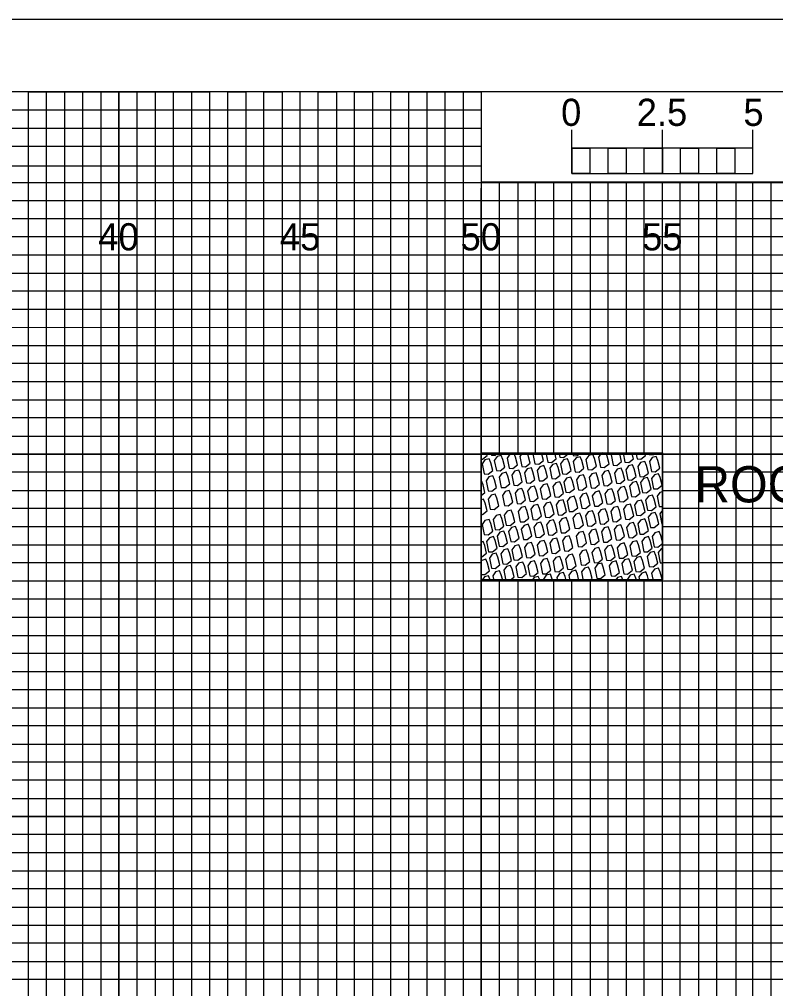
# Model space of a CAD drawing. Extents: x -7 to 193, y -2 to 107.
# Drawn here: x 117.25 to 138.13, y 80.25 to 107 of the extents above; entities that cross this region are included whole.
import ezdxf

# ---------------------------------------------------------------- set-up
doc = ezdxf.new("R2010")
doc.units = 0
for name, color, linetype in [('Exist XS Center Line Elevation Label', 7, 'Continuous'), ('Old_Level_1', 7, 'Continuous'), ('Prop Vertical Profile Curve Label', 7, 'Continuous'), ('Prop XS Bar Scale Labels', 7, 'Continuous'), ('Prop XS Offset Labels', 7, 'Continuous'), ('Sheet Cross Section CELL', 7, 'Continuous'), ('Sheet Cross Section Grid Major CELL', 7, 'Continuous'), ('Sheet Cross Section Grid Middle CELL', 7, 'Continuous'), ('Sheet Cross Section Grid Minor 1 CELL', 7, 'Continuous'), ('Sheet Cross Section Grid Minor 2 CELL', 7, 'Continuous'), ('Sheet Cross Section Scale CELL', 7, 'Continuous'), ('Sheet Cutting Line CELL', 7, 'Continuous'), ('Sheet DOT Grid CELL', 7, 'Continuous'), ('Sheet Plot Border Inside CELL', 7, 'Continuous'), ('Sheet Plot Border Outside CELL', 7, 'Continuous')]:
    doc.layers.add(name, color=color, linetype=linetype)

msp = doc.modelspace()

# ---------------------------------------------------------------- linework, layer by layer
at = {"layer": 'Old_Level_1'}
for points in [[(130, 94.864), (130.035, 94.862), (130.164, 94.965), (130.146, 95.034)], [(130.268, 95.034), (130.28, 94.976), (130.385, 94.968), (130.467, 95.034)], [(130.643, 95.034), (130.645, 95.022), (130.751, 95.014), (130.775, 95.034)], [(131.133, 95.034), (131.062, 94.936), (131.118, 94.656), (131.223, 94.648), (131.353, 94.752), (131.298, 94.962), (131.269, 95.034)], [(131.443, 95.034), (131.428, 95.012), (131.483, 94.732), (131.589, 94.725), (131.718, 94.828), (131.665, 95.034)], [(131.783, 95.034), (131.834, 94.778), (131.939, 94.77), (132.069, 94.874), (132.027, 95.034)], [(132.145, 95.034), (132.169, 94.915), (132.274, 94.907), (132.404, 95.011), (132.398, 95.034)], [(132.52, 95.034), (132.535, 94.961), (132.64, 94.953), (132.741, 95.034)], [(133.348, 95.034), (133.314, 95.025), (133.237, 94.919), (133.293, 94.639), (133.398, 94.631), (133.528, 94.734), (133.473, 94.945), (133.437, 95.034)], [(133.625, 95.034), (133.586, 94.98), (133.641, 94.7), (133.747, 94.692), (133.876, 94.796), (133.822, 95.006), (133.811, 95.034)], [(133.916, 95.034), (133.967, 94.778), (134.072, 94.77), (134.202, 94.874), (134.16, 95.034)], [(134.269, 95.034), (134.302, 94.869), (134.407, 94.862), (134.537, 94.965), (134.519, 95.034)], [(134.629, 95.034), (134.637, 94.991), (134.742, 94.984), (134.805, 95.034)], [(130, 93.861), (130.103, 93.944), (130.049, 94.154), (130.004, 94.264), (130, 94.263)], [(132.336, 93.95), (132.441, 93.942), (132.571, 94.046), (132.516, 94.256), (132.471, 94.366), (132.357, 94.336), (132.28, 94.23), (132.336, 93.95)], [(132.685, 94.012), (132.79, 94.004), (132.919, 94.107), (132.865, 94.318), (132.82, 94.427), (132.706, 94.398), (132.629, 94.292), (132.685, 94.012)], [(130.64, 93.58), (130.745, 93.572), (130.874, 93.675), (130.82, 93.886), (130.775, 93.996), (130.661, 93.966), (130.584, 93.86), (130.64, 93.58)], [(130.988, 93.641), (131.094, 93.634), (131.223, 93.737), (131.169, 93.947), (131.123, 94.057), (131.01, 94.028), (130.933, 93.921), (130.988, 93.641)], [(133.122, 93.569), (133.227, 93.561), (133.357, 93.664), (133.302, 93.875), (133.257, 93.985), (133.144, 93.955), (133.066, 93.849), (133.122, 93.569)], [(133.471, 93.63), (133.576, 93.623), (133.705, 93.726), (133.651, 93.937), (133.606, 94.046), (133.492, 94.017), (133.415, 93.91), (133.471, 93.63)], [(133.819, 93.692), (133.925, 93.684), (134.054, 93.787), (134, 93.998), (133.954, 94.108), (133.841, 94.078), (133.764, 93.972), (133.819, 93.692)], [(135, 93.962), (134.933, 93.945), (134.856, 93.839), (134.911, 93.559), (135, 93.552)], [(130, 93.34), (130.035, 93.338), (130.164, 93.441), (130.11, 93.651), (130.065, 93.761), (130, 93.744)], [(131.774, 93.26), (131.88, 93.252), (132.009, 93.356), (131.955, 93.566), (131.91, 93.676), (131.796, 93.647), (131.719, 93.54), (131.774, 93.26)], [(132.123, 93.322), (132.228, 93.314), (132.358, 93.417), (132.303, 93.628), (132.258, 93.737), (132.144, 93.708), (132.067, 93.602), (132.123, 93.322)], [(131.426, 93.199), (131.531, 93.191), (131.661, 93.294), (131.606, 93.505), (131.561, 93.614), (131.447, 93.585), (131.37, 93.479), (131.426, 93.199)], [(135.005, 93.451), (134.932, 93.351), (134.988, 93.071), (135.005, 93.07)], [(132.675, 92.454), (132.781, 92.446), (132.91, 92.549), (132.856, 92.76), (132.81, 92.869), (132.697, 92.84), (132.62, 92.733), (132.675, 92.454)], [(133.024, 92.515), (133.129, 92.507), (133.259, 92.611), (133.204, 92.821), (133.159, 92.931), (133.045, 92.901), (132.968, 92.795), (133.024, 92.515)], [(130, 92.165), (130.019, 92.164), (130.149, 92.267), (130.095, 92.478), (130.049, 92.587), (130, 92.575)], [(131.25, 92.145), (131.356, 92.137), (131.485, 92.24), (131.431, 92.451), (131.386, 92.561), (131.272, 92.531), (131.195, 92.425), (131.25, 92.145)], [(134.159, 92.195), (134.264, 92.188), (134.393, 92.291), (134.339, 92.501), (134.294, 92.611), (134.18, 92.582), (134.103, 92.475), (134.159, 92.195)], [(130.902, 92.083), (131.007, 92.076), (131.137, 92.179), (131.082, 92.389), (131.037, 92.499), (130.923, 92.47), (130.846, 92.363), (130.902, 92.083)], [(133.461, 92.072), (133.567, 92.065), (133.696, 92.168), (133.642, 92.379), (133.597, 92.488), (133.483, 92.459), (133.406, 92.352), (133.461, 92.072)], [(133.81, 92.134), (133.915, 92.126), (134.045, 92.229), (133.99, 92.44), (133.945, 92.55), (133.831, 92.52), (133.754, 92.414), (133.81, 92.134)], [(135, 92.4), (134.963, 92.39), (134.886, 92.284), (134.942, 92.004), (135, 92)], [(130, 91.683), (130.096, 91.676), (130.225, 91.779), (130.171, 91.99), (130.126, 92.1), (130.012, 92.07), (130, 92.054)], [(131.688, 91.702), (131.793, 91.694), (131.923, 91.798), (131.868, 92.008), (131.823, 92.118), (131.709, 92.089), (131.632, 91.982), (131.688, 91.702)], [(132.036, 91.764), (132.142, 91.756), (132.271, 91.859), (132.217, 92.07), (132.172, 92.179), (132.058, 92.15), (131.981, 92.044), (132.036, 91.764)], [(132.385, 91.825), (132.49, 91.817), (132.62, 91.921), (132.565, 92.131), (132.52, 92.241), (132.407, 92.211), (132.329, 92.105), (132.385, 91.825)], [(130.583, 91.549), (130.552, 91.67), (130.506, 91.779), (130.393, 91.75), (130.316, 91.644), (130.334, 91.549)], [(130.832, 91.549), (130.911, 91.612), (130.856, 91.822), (130.811, 91.932), (130.697, 91.903), (130.62, 91.796), (130.669, 91.549)], [(132.689, 91.549), (132.654, 91.685), (132.609, 91.795), (132.495, 91.765), (132.418, 91.659), (132.44, 91.549)], [(133.037, 91.549), (133.059, 91.566), (133.004, 91.776), (132.959, 91.886), (132.846, 91.857), (132.768, 91.75), (132.809, 91.549)], [(134.99, 91.549), (134.939, 91.746), (134.894, 91.856), (134.78, 91.826), (134.703, 91.72), (134.737, 91.549)], [(130.24, 91.549), (130.202, 91.642), (130.088, 91.613), (130.041, 91.549)], [(131.605, 91.549), (131.573, 91.627), (131.459, 91.598), (131.424, 91.549)], [(131.961, 91.549), (131.953, 91.578), (131.908, 91.688), (131.794, 91.659), (131.717, 91.552), (131.718, 91.549)], [(132.338, 91.549), (132.319, 91.624), (132.274, 91.734), (132.16, 91.704), (132.083, 91.598), (132.093, 91.549)], [(133.912, 91.534), (133.873, 91.627), (133.76, 91.598), (133.713, 91.534)], [(134.277, 91.549), (134.269, 91.578), (134.224, 91.688), (134.11, 91.659), (134.033, 91.552), (134.034, 91.549)], [(134.616, 91.534), (134.589, 91.639), (134.544, 91.749), (134.43, 91.72), (134.353, 91.613), (134.369, 91.534)]]:
    msp.add_lwpolyline(points, dxfattribs=at)
for points in [[(130.417, 94.549), (130.522, 94.542), (130.652, 94.645), (130.597, 94.855), (130.552, 94.965), (130.438, 94.936), (130.361, 94.829)], [(130.417, 94.549), (130.522, 94.542), (130.652, 94.645), (130.597, 94.855), (130.552, 94.965), (130.438, 94.936), (130.361, 94.829)], [(130.767, 94.61), (130.873, 94.603), (131.002, 94.706), (130.948, 94.916), (130.903, 95.026), (130.789, 94.997), (130.712, 94.89)], [(130.767, 94.61), (130.873, 94.603), (131.002, 94.706), (130.948, 94.916), (130.903, 95.026), (130.789, 94.997), (130.712, 94.89)], [(132.944, 94.577), (133.05, 94.569), (133.179, 94.673), (133.125, 94.883), (133.079, 94.993), (132.966, 94.963), (132.889, 94.857)], [(130.082, 94.458), (130.187, 94.45), (130.317, 94.553), (130.262, 94.764), (130.217, 94.874), (130.103, 94.844), (130.026, 94.738)], [(130.082, 94.458), (130.187, 94.45), (130.317, 94.553), (130.262, 94.764), (130.217, 94.874), (130.103, 94.844), (130.026, 94.738)], [(131.945, 94.33), (132.05, 94.322), (132.18, 94.425), (132.126, 94.636), (132.08, 94.746), (131.967, 94.716), (131.89, 94.61)], [(132.247, 94.454), (132.352, 94.446), (132.482, 94.55), (132.427, 94.76), (132.382, 94.87), (132.269, 94.841), (132.191, 94.734)], [(132.596, 94.516), (132.701, 94.508), (132.83, 94.611), (132.776, 94.822), (132.731, 94.931), (132.617, 94.902), (132.54, 94.796)], [(134.043, 94.29), (134.148, 94.283), (134.278, 94.386), (134.223, 94.596), (134.178, 94.706), (134.064, 94.677), (133.987, 94.57)], [(134.378, 94.382), (134.483, 94.374), (134.613, 94.477), (134.558, 94.688), (134.513, 94.797), (134.4, 94.768), (134.322, 94.662)], [(134.698, 94.519), (134.803, 94.511), (134.933, 94.614), (134.878, 94.825), (134.833, 94.935), (134.719, 94.905), (134.642, 94.799)], [(130.551, 94.084), (130.656, 94.076), (130.786, 94.179), (130.731, 94.39), (130.686, 94.5), (130.572, 94.47), (130.495, 94.364)], [(130.899, 94.145), (131.005, 94.138), (131.134, 94.241), (131.08, 94.451), (131.035, 94.561), (130.921, 94.532), (130.844, 94.425)], [(131.248, 94.207), (131.353, 94.199), (131.483, 94.302), (131.428, 94.513), (131.383, 94.623), (131.269, 94.593), (131.192, 94.487)], [(131.597, 94.268), (131.702, 94.261), (131.831, 94.364), (131.777, 94.574), (131.732, 94.684), (131.618, 94.655), (131.541, 94.548)], [(133.033, 94.073), (133.138, 94.065), (133.268, 94.169), (133.214, 94.379), (133.168, 94.489), (133.055, 94.459), (132.978, 94.353)], [(133.382, 94.134), (133.487, 94.127), (133.617, 94.23), (133.562, 94.441), (133.517, 94.55), (133.403, 94.521), (133.326, 94.414)], [(133.73, 94.196), (133.836, 94.188), (133.965, 94.291), (133.911, 94.502), (133.866, 94.612), (133.752, 94.582), (133.675, 94.476)], [(134.759, 94.046), (134.864, 94.039), (134.994, 94.142), (134.939, 94.352), (134.894, 94.462), (134.78, 94.433), (134.703, 94.326)], [(130.188, 93.985), (130.294, 93.978), (130.423, 94.081), (130.369, 94.291), (130.324, 94.401), (130.21, 94.372), (130.133, 94.265)], [(131.685, 93.764), (131.791, 93.757), (131.92, 93.86), (131.866, 94.07), (131.821, 94.18), (131.707, 94.151), (131.63, 94.044)], [(132.034, 93.826), (132.139, 93.818), (132.269, 93.921), (132.214, 94.132), (132.169, 94.241), (132.055, 94.212), (131.978, 94.106)], [(134.15, 93.833), (134.255, 93.825), (134.384, 93.928), (134.33, 94.139), (134.285, 94.249), (134.171, 94.219), (134.094, 94.113)], [(134.454, 93.94), (134.56, 93.932), (134.689, 94.035), (134.635, 94.246), (134.589, 94.355), (134.476, 94.326), (134.399, 94.22)], [(130.249, 93.482), (130.355, 93.475), (130.484, 93.578), (130.43, 93.788), (130.385, 93.898), (130.271, 93.869), (130.194, 93.762)], [(131.337, 93.703), (131.442, 93.695), (131.572, 93.798), (131.517, 94.009), (131.472, 94.119), (131.358, 94.089), (131.281, 93.983)], [(132.773, 93.507), (132.879, 93.5), (133.008, 93.603), (132.954, 93.814), (132.909, 93.923), (132.795, 93.894), (132.718, 93.787)], [(132.428, 93.421), (132.533, 93.414), (132.663, 93.517), (132.608, 93.728), (132.563, 93.837), (132.449, 93.808), (132.372, 93.701)], [(134.287, 93.315), (134.392, 93.307), (134.521, 93.41), (134.467, 93.621), (134.422, 93.731), (134.308, 93.701), (134.231, 93.595)], [(134.591, 93.452), (134.697, 93.444), (134.826, 93.547), (134.772, 93.758), (134.727, 93.868), (134.613, 93.838), (134.536, 93.732)], [(130.691, 93.04), (130.796, 93.033), (130.926, 93.136), (130.872, 93.346), (130.826, 93.456), (130.713, 93.427), (130.636, 93.32)], [(131.077, 93.137), (131.182, 93.13), (131.312, 93.233), (131.257, 93.443), (131.212, 93.553), (131.099, 93.524), (131.022, 93.417)], [(132.586, 92.958), (132.692, 92.95), (132.821, 93.053), (132.767, 93.264), (132.722, 93.373), (132.608, 93.344), (132.531, 93.238)], [(132.935, 93.019), (133.04, 93.011), (133.17, 93.115), (133.115, 93.325), (133.07, 93.435), (132.956, 93.405), (132.879, 93.299)], [(133.284, 93.081), (133.389, 93.073), (133.518, 93.176), (133.464, 93.387), (133.419, 93.496), (133.305, 93.467), (133.228, 93.361)], [(133.632, 93.142), (133.737, 93.134), (133.867, 93.238), (133.813, 93.448), (133.767, 93.558), (133.654, 93.528), (133.577, 93.422)], [(133.981, 93.203), (134.086, 93.196), (134.216, 93.299), (134.161, 93.51), (134.116, 93.619), (134.002, 93.59), (133.925, 93.483)], [(134.668, 92.979), (134.773, 92.972), (134.902, 93.075), (134.848, 93.285), (134.803, 93.395), (134.689, 93.366), (134.612, 93.259)], [(130.082, 92.781), (130.187, 92.774), (130.317, 92.877), (130.262, 93.087), (130.217, 93.197), (130.103, 93.168), (130.026, 93.061)], [(130.386, 92.918), (130.492, 92.911), (130.621, 93.014), (130.567, 93.225), (130.522, 93.334), (130.408, 93.305), (130.331, 93.198)], [(131.51, 92.71), (131.615, 92.703), (131.745, 92.806), (131.69, 93.016), (131.645, 93.126), (131.532, 93.097), (131.455, 92.99)], [(131.859, 92.772), (131.964, 92.764), (132.094, 92.867), (132.039, 93.078), (131.994, 93.188), (131.88, 93.158), (131.803, 93.052)], [(132.207, 92.833), (132.313, 92.826), (132.442, 92.929), (132.388, 93.139), (132.343, 93.249), (132.229, 93.22), (132.152, 93.113)], [(134.07, 92.699), (134.175, 92.692), (134.304, 92.795), (134.25, 93.006), (134.205, 93.115), (134.091, 93.086), (134.014, 92.979)], [(134.378, 92.796), (134.483, 92.789), (134.613, 92.892), (134.558, 93.103), (134.513, 93.212), (134.4, 93.183), (134.322, 93.076)], [(130.493, 92.461), (130.598, 92.453), (130.728, 92.557), (130.673, 92.767), (130.628, 92.877), (130.515, 92.848), (130.437, 92.741)], [(130.813, 92.587), (130.918, 92.58), (131.048, 92.683), (130.993, 92.893), (130.948, 93.003), (130.834, 92.974), (130.757, 92.867)], [(131.162, 92.649), (131.267, 92.641), (131.396, 92.744), (131.342, 92.955), (131.297, 93.065), (131.183, 93.035), (131.106, 92.929)], [(133.372, 92.576), (133.478, 92.569), (133.607, 92.672), (133.553, 92.883), (133.508, 92.992), (133.394, 92.963), (133.317, 92.856)], [(133.721, 92.638), (133.826, 92.63), (133.956, 92.733), (133.901, 92.944), (133.856, 93.054), (133.742, 93.024), (133.665, 92.918)], [(134.774, 92.446), (134.879, 92.438), (135.009, 92.541), (134.955, 92.752), (134.909, 92.862), (134.796, 92.832), (134.719, 92.726)], [(130.204, 92.309), (130.309, 92.301), (130.438, 92.404), (130.384, 92.615), (130.339, 92.725), (130.225, 92.695), (130.148, 92.589)], [(131.599, 92.206), (131.704, 92.199), (131.834, 92.302), (131.779, 92.512), (131.734, 92.622), (131.62, 92.593), (131.543, 92.486)], [(131.948, 92.268), (132.053, 92.26), (132.182, 92.363), (132.128, 92.574), (132.083, 92.683), (131.969, 92.654), (131.892, 92.548)], [(132.296, 92.329), (132.401, 92.321), (132.531, 92.425), (132.477, 92.635), (132.431, 92.745), (132.318, 92.716), (132.241, 92.609)], [(134.485, 92.309), (134.59, 92.301), (134.72, 92.404), (134.665, 92.615), (134.62, 92.725), (134.506, 92.695), (134.429, 92.589)], [(130.6, 91.973), (130.705, 91.966), (130.835, 92.069), (130.78, 92.279), (130.735, 92.389), (130.621, 92.36), (130.544, 92.253)], [(132.763, 91.943), (132.868, 91.935), (132.998, 92.038), (132.944, 92.249), (132.898, 92.359), (132.785, 92.329), (132.708, 92.223)], [(133.113, 92.011), (133.218, 92.003), (133.348, 92.106), (133.293, 92.317), (133.248, 92.427), (133.134, 92.397), (133.057, 92.291)], [(134.637, 91.897), (134.742, 91.889), (134.872, 91.993), (134.817, 92.203), (134.772, 92.313), (134.659, 92.284), (134.581, 92.177)], [(130.28, 91.851), (130.385, 91.844), (130.515, 91.947), (130.46, 92.158), (130.415, 92.267), (130.301, 92.238), (130.224, 92.131)], [(131.011, 91.608), (131.116, 91.6), (131.246, 91.703), (131.191, 91.914), (131.146, 92.023), (131.033, 91.994), (130.955, 91.888)], [(131.339, 91.641), (131.445, 91.633), (131.574, 91.736), (131.52, 91.947), (131.474, 92.056), (131.361, 92.027), (131.284, 91.921)], [(133.586, 91.638), (133.691, 91.63), (133.821, 91.734), (133.766, 91.944), (133.721, 92.054), (133.607, 92.024), (133.53, 91.918)], [(133.936, 91.699), (134.042, 91.691), (134.171, 91.795), (134.117, 92.005), (134.071, 92.115), (133.958, 92.085), (133.881, 91.979)], [(134.271, 91.76), (134.377, 91.752), (134.506, 91.856), (134.452, 92.066), (134.407, 92.176), (134.293, 92.146), (134.216, 92.04)], [(133.19, 91.577), (133.295, 91.569), (133.425, 91.673), (133.37, 91.883), (133.325, 91.993), (133.211, 91.963), (133.134, 91.857)]]:
    msp.add_lwpolyline(points, close=True, dxfattribs=at)
at = {"layer": 'Prop Vertical Profile Curve Label'}
for p, q in [((130, 95.034), (135, 95.034)), ((130, 91.534), (130, 95.034)), ((135, 95.034), (135, 91.534)), ((135, 91.534), (130, 91.534))]:
    msp.add_line(p, q, dxfattribs=at)
at = {"layer": 'Sheet Cross Section CELL'}
for points in [[(160, 105), (0, 105), (0, 0), (160, 0)], [(140, 105), (130, 105), (130, 102.515), (140, 102.515)]]:
    msp.add_lwpolyline(points, close=True, dxfattribs=at)
at = {"layer": 'Sheet Cross Section Grid Major CELL'}
for p, q in [((125, 105), (120, 105)), ((120, 105), (120, 0)), ((125, 0), (125, 105)), ((130, 105), (130, 0)), ((135, 0), (135, 102.5))]:
    msp.add_line(p, q, dxfattribs=at)
for points in [[(0, 100), (160, 100), (160, 95), (0, 95)], [(0, 90), (160, 90), (160, 85), (0, 85)]]:
    msp.add_lwpolyline(points, dxfattribs=at)
at = {"layer": 'Sheet Cross Section Grid Middle CELL'}
for points in [[(92.5, 0), (97.5, 0), (97.5, 105), (102.5, 105), (102.5, 0), (107.5, 0), (107.5, 105), (112.5, 105), (112.5, 0), (117.5, 0), (117.5, 105), (122.5, 105), (122.5, 0), (127.5, 0), (127.5, 105), (129.965, 105), (130, 105), (130, 102.5), (132.495, 102.5), (132.495, 95.034)], [(0, 102.5), (137.5, 102.5)], [(132.495, 91.5), (132.495, 0), (137.5, 0), (137.5, 102.5), (142.5, 102.5), (142.5, 0), (147.5, 0), (147.5, 102.5), (152.5, 102.5), (152.5, 0), (157.5, 0), (157.5, 102.5)], [(135, 92.5), (160, 92.5), (160, 97.5), (0, 97.5)], [(0, 92.5), (130, 92.5)], [(0, 82.5), (160, 82.5), (160, 87.5), (0, 87.5)]]:
    msp.add_lwpolyline(points, dxfattribs=at)
at = {"layer": 'Sheet Cross Section Grid Minor 1 CELL'}
for p, q in [((0, 104.5), (130, 104.5)), ((130, 104.5), (130, 103.99)), ((130, 103.99), (0, 103.99)), ((0, 103.5), (130, 103.5)), ((130, 103.5), (130, 102.945)), ((130, 102.945), (0, 102.945)), ((0, 102), (160, 102))]:
    msp.add_line(p, q, dxfattribs=at)
for points in [[(0, 101.5), (135, 101.5), (160, 101.5), (160, 101), (0, 101)], [(0, 100.5), (160, 100.5), (160, 99.5), (0, 99.5)], [(0, 99), (160, 99), (160, 98.5), (0, 98.49)], [(0, 98), (160, 98), (160, 97), (0, 97)], [(0, 96.5), (160, 96.5), (160, 96), (0, 96)], [(0, 95.5), (160, 95.5), (160, 94.5), (135, 94.5)], [(130, 94.5), (0, 94.5)], [(0, 94), (130, 94)], [(135, 94), (160, 94), (160, 93.5), (135, 93.5)], [(130, 93.5), (0, 93.5)], [(0, 93), (130, 93)], [(135, 93), (160, 93), (160, 92), (135, 92)], [(130, 92), (0, 92)], [(0, 91.5), (160, 91.5), (160, 91), (0, 91)], [(0, 90.5), (160, 90.5), (160, 89.5), (0, 89.5)], [(0, 89), (160, 89), (160, 88.5), (0, 88.5)], [(0, 88), (160, 88), (160, 86.975), (160, 86.5), (160, 86), (0, 86)], [(0, 87), (160, 87), (160, 86.5), (0, 86.5)], [(0, 85.5), (160, 85.5), (160, 84.5), (0, 84.515)], [(0, 84.515), (160, 84.5), (160, 84), (0, 84)], [(0, 83.5), (160, 83.5), (160, 83), (0, 83)], [(0, 82), (160, 82), (160, 81.5), (0, 81.5)], [(0, 81), (160, 81), (160, 80.5), (0, 80.5)]]:
    msp.add_lwpolyline(points, dxfattribs=at)
at = {"layer": 'Sheet Cross Section Grid Minor 2 CELL'}
for p, q in [((133.5, 102.5), (133.005, 102.5)), ((133.005, 102.5), (133.005, 95.034)), ((133.5, 95.034), (133.5, 102.5)), ((134.5, 102.5), (134, 102.5)), ((134, 102.5), (134, 95.034)), ((134.5, 95.034), (134.5, 102.5)), ((133.005, 91.5), (133.005, 0)), ((133.5, 0), (133.5, 91.5)), ((134, 91.5), (134, 0)), ((134.5, 0), (134.5, 91.5))]:
    msp.add_line(p, q, dxfattribs=at)
for points in [[(117.5, 0), (118, 0), (118, 105), (118.5, 105), (118.5, 0)], [(118.5, 0), (119, 0), (119, 105), (119.5, 105), (119.5, 0)], [(120, 0), (120.5, 0), (120.5, 105), (121, 105), (121, 0)], [(121, 0), (121.5, 0), (121.5, 105), (122, 105), (122, 0)], [(122.5, 0), (123, 0), (123, 105), (123.5, 105), (123.5, 0)], [(123.5, 0), (124, 0), (124, 105), (124.5, 105), (124.5, 0)], [(125, 0), (125.5, 0), (125.5, 105), (126, 105), (126, 0)], [(126, 0), (126.5, 0), (126.5, 105), (127, 105), (127, 0)], [(127.5, 0), (128, 0), (128, 105), (128.5, 105), (128.5, 0)], [(128.5, 0), (129, 0), (129, 105), (129.5, 105), (129.5, 0)], [(130.5, 95.034), (130.5, 102.5), (131.01, 102.5), (131.01, 95.034)], [(131.5, 95.034), (131.5, 102.5), (131.995, 102.5), (131.995, 95.034)], [(135, 0), (135.49, 0), (135.49, 102.5), (136, 102.5), (136, 0)], [(136, 0), (136.5, 0), (136.5, 102.5), (137.025, 102.5), (137.025, 0)], [(137.5, 0), (138, 0), (138, 102.5), (138.5, 102.5), (138.5, 0)], [(130, 0), (130.5, 0), (130.5, 91.5)], [(131, 0), (131.5, 0), (131.5, 91.5)], [(131.01, 91.5), (131.01, 0)], [(131.995, 91.5), (131.995, 0)]]:
    msp.add_lwpolyline(points, dxfattribs=at)
at = {"layer": 'Sheet Cross Section Scale CELL'}
for p, q in [((132.5, 102.745), (132.5, 103.95)), ((132.5, 103.45), (132.5, 103.95)), ((135, 102.745), (135, 103.95)), ((137.5, 102.745), (137.5, 103.95)), ((137.5, 103.45), (137.5, 103.95))]:
    msp.add_line(p, q, dxfattribs=at)
for points in [[(137.5, 103.45), (132.5, 103.45), (132.5, 102.745), (137.5, 102.745)], [(132.5, 103.45), (133, 103.45), (133, 102.745), (132.5, 102.745)], [(133.5, 103.45), (134, 103.45), (134, 102.745), (133.5, 102.745)], [(134.5, 103.45), (135, 103.45), (135, 102.745), (134.5, 102.745)], [(135.5, 103.45), (136, 103.45), (136, 102.745), (135.5, 102.745)], [(136.5, 103.45), (137, 103.45), (137, 102.745), (136.5, 102.745)]]:
    msp.add_lwpolyline(points, close=True, dxfattribs=at)
at = {"layer": 'Sheet Cutting Line CELL'}
msp.add_line((161.65, 107), (-6.7, 107), dxfattribs=at)
at = {"layer": 'Sheet DOT Grid CELL'}
for p, q in [((120, 0), (120, 105)), ((125, 0), (125, 105)), ((130, 0), (130, 102.343)), ((135, 0), (135, 102.343)), ((0, 100), (160, 100)), ((0, 95), (160, 95)), ((0, 90), (160, 90)), ((0, 85), (160, 85))]:
    msp.add_line(p, q, dxfattribs=at)
at = {"layer": 'Sheet Plot Border Inside CELL'}
msp.add_lwpolyline([(-5.4, -0.5), (161.2, -0.5), (161.2, 105), (-5.4, 105)], close=True, dxfattribs=at)
at = {"layer": 'Sheet Plot Border Outside CELL'}
msp.add_lwpolyline([(-6.7, -2.5), (161.65, -2.5), (161.65, 107), (-6.7, 107)], close=True, dxfattribs=at)

# ---------------------------------------------------------------- texts
at = {"layer": 'Exist XS Center Line Elevation Label'}
msp.add_text('ROCK EMBANKMENTS -', height=1, dxfattribs=at).set_placement((135.901, 93.669))
at = {"layer": 'Prop XS Bar Scale Labels'}
for s, p in [('2.5', (134.292, 104.06)), ('5', (137.237, 104.06))]:
    msp.add_text(s, height=0.75, dxfattribs=at).set_placement(p)
at = {"layer": 'Prop XS Offset Labels'}
for s, p in [('40', (119.429, 100.625)), ('50', (129.429, 100.625)), ('45', (124.441, 100.625)), ('55', (134.441, 100.625))]:
    msp.add_text(s, height=0.75, dxfattribs=at).set_placement(p)
at = {"layer": 'Sheet Cross Section Scale CELL'}
msp.add_text('0', height=0.75, dxfattribs=at).set_placement((132.205, 104.06))

doc.saveas('drawing.dxf')
